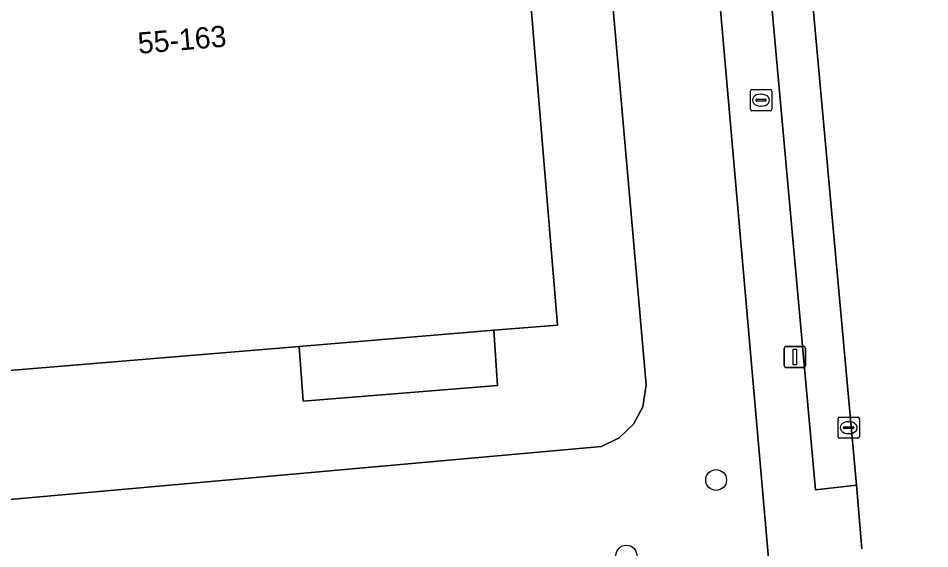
# Model space of a CAD drawing. Extents: x 162989 to 165008, y 383432 to 384338.
# Drawn here: x 164281.81 to 164324.59, y 383867.76 to 383892.69 of the extents above; entities that cross this region are included whole.
import ezdxf

# ---------------------------------------------------------------- set-up
doc = ezdxf.new("R2010")
doc.units = 0
for name, color, linetype in [('IMGEO_Boom', 7, 'Continuous'), ('IMGEO_Brandkraan', 7, 'Continuous'), ('IMGEO_Groenvoorziening', 7, 'Continuous'), ('IMGEO_Kolk', 7, 'Continuous'), ('IMGEO_Lichtmast', 7, 'Continuous'), ('IMGEO_Pand', 7, 'Continuous'), ('IMGEO_Pand_nummerreeks', 7, 'Continuous'), ('IMGEO_Parkeervlak_open', 7, 'Continuous'), ('IMGEO_Rijbaan_lokaal_open', 7, 'Continuous'), ('IMGEO_Voetpad_open', 7, 'Continuous')]:
    doc.layers.add(name, color=color, linetype=linetype)

msp = doc.modelspace()

# ---------------------------------------------------------------- linework, layer by layer
at = {"layer": 'IMGEO_Boom'}
for centre in [(164314.563, 383870.989), (164310.352, 383867.439)]:
    msp.add_circle(centre, 0.489, dxfattribs=at)
at = {"layer": 'IMGEO_Brandkraan'}
for p, q in [((164316.244, 383889.335), (164317.096, 383889.335)), ((164316.169, 383888.409), (164316.169, 383889.261)), ((164316.657, 383889.115), (164316.682, 383889.115)), ((164317.17, 383889.261), (164317.17, 383888.409)), ((164316.428, 383888.829), (164316.428, 383888.841)), ((164316.866, 383888.792), (164316.468, 383888.792)), ((164316.471, 383888.878), (164316.869, 383888.878)), ((164316.68, 383888.555), (164316.655, 383888.555)), ((164316.912, 383888.841), (164316.912, 383888.829)), ((164317.096, 383888.335), (164316.244, 383888.335))]:
    msp.add_line(p, q, dxfattribs=at)
for points in [[(164316.244, 383889.335), (164317.096, 383889.335)], [(164316.169, 383888.409), (164316.169, 383889.261)], [(164317.17, 383889.261), (164317.17, 383888.409)], [(164317.096, 383888.335), (164316.244, 383888.335)]]:
    msp.add_lwpolyline(points, dxfattribs=at)
for centre, radius, start, end in [((164316.246, 383889.259), 0.0765, 91.552, 178.448), ((164316.246, 383889.259), 0.0765, 91.552, 178.448), ((164317.094, 383889.259), 0.0765, 1.552, 88.448), ((164317.094, 383889.259), 0.0765, 1.552, 88.448), ((164316.468, 383888.838), 0.0403, 85.8775, 175.7526), ((164316.465, 383888.828), 0.0366, 178.938, 274.7102), ((164316.869, 383888.835), 0.043, 264.8664, 352.4533), ((164316.873, 383888.84), 0.0386, 1.7309, 96.639), ((164316.246, 383888.411), 0.0765, 181.552, 268.448), ((164316.246, 383888.411), 0.0765, 181.552, 268.448), ((164317.094, 383888.411), 0.0765, 271.552, 358.448), ((164317.094, 383888.411), 0.0765, 271.552, 358.448)]:
    msp.add_arc(centre, radius, start, end, dxfattribs=at)
for centre, major_axis, ratio, start_param, end_param in [((164316.656, 383888.835), (-0.387, 0.002), 0.722429, 4.712389, 7.853982), ((164316.681, 383888.835), (-0.39, 0.002), 0.717154, 1.570796, 4.712389)]:
    msp.add_ellipse(centre, major_axis=major_axis, ratio=ratio, start_param=start_param, end_param=end_param, dxfattribs=at)
at = {"layer": 'IMGEO_Groenvoorziening'}
for points in [[(164311.621, 383906.595), (164309.285, 383906.355), (164307.801, 383906.262), (164304.812, 383906.003), (164307.113, 383878.271), (164304.123, 383878.023), (164304.31, 383875.425), (164295.181, 383874.701), (164294.997, 383877.265), (164276.472, 383875.728), (164274.745, 383896.542)], [(164271.417, 383894.215), (164273.539, 383869.365), (164309.188, 383872.569), (164310.019, 383872.973), (164310.684, 383873.614), (164311.118, 383874.429), (164311.279, 383875.468), (164308.972, 383901.858), (164313.975, 383902.213), (164313.728, 383905.024)], [(164317.115, 383866.231), (164313.975, 383902.213), (164308.972, 383901.858), (164311.279, 383875.468), (164311.118, 383874.429), (164310.684, 383873.614), (164310.019, 383872.973), (164309.188, 383872.569), (164273.539, 383869.365), (164274.024, 383863.683)]]:
    msp.add_lwpolyline(points, dxfattribs=at)
at = {"layer": 'IMGEO_Kolk'}
for p, q in [((164320.361, 383873.948), (164321.213, 383873.948)), ((164320.286, 383873.022), (164320.286, 383873.874)), ((164320.588, 383873.491), (164320.986, 383873.491)), ((164320.774, 383873.728), (164320.799, 383873.728)), ((164321.287, 383873.874), (164321.287, 383873.022)), ((164320.545, 383873.442), (164320.545, 383873.454)), ((164320.983, 383873.405), (164320.585, 383873.405)), ((164320.797, 383873.168), (164320.772, 383873.168)), ((164321.029, 383873.454), (164321.029, 383873.442)), ((164321.213, 383872.948), (164320.361, 383872.948))]:
    msp.add_line(p, q, dxfattribs=at)
for points in [[(164320.361, 383873.948), (164321.213, 383873.948)], [(164320.286, 383873.022), (164320.286, 383873.874)], [(164321.287, 383873.874), (164321.287, 383873.022)], [(164321.213, 383872.948), (164320.361, 383872.948)]]:
    msp.add_lwpolyline(points, dxfattribs=at)
for centre, radius, start, end in [((164320.363, 383873.872), 0.0765, 91.552, 178.448), ((164320.363, 383873.872), 0.0765, 91.552, 178.448), ((164321.211, 383873.872), 0.0765, 1.552, 88.448), ((164321.211, 383873.872), 0.0765, 1.552, 88.448), ((164320.585, 383873.451), 0.0403, 85.8775, 175.7526), ((164320.99, 383873.453), 0.0386, 1.7309, 96.639), ((164320.582, 383873.441), 0.0366, 178.938, 274.7102), ((164320.986, 383873.448), 0.043, 264.8664, 352.4533), ((164320.363, 383873.024), 0.0765, 181.552, 268.448), ((164320.363, 383873.024), 0.0765, 181.552, 268.448), ((164321.211, 383873.024), 0.0765, 271.552, 358.448), ((164321.211, 383873.024), 0.0765, 271.552, 358.448)]:
    msp.add_arc(centre, radius, start, end, dxfattribs=at)
for centre, major_axis, ratio, start_param, end_param in [((164320.773, 383873.448), (-0.387, 0.002), 0.722429, 4.712389, 7.853982), ((164320.798, 383873.448), (-0.39, 0.002), 0.717154, 1.570796, 4.712389)]:
    msp.add_ellipse(centre, major_axis=major_axis, ratio=ratio, start_param=start_param, end_param=end_param, dxfattribs=at)
at = {"layer": 'IMGEO_Lichtmast'}
for p, q in [((164317.76, 383876.368), (164317.76, 383877.168)), ((164317.76, 383877.168), (164317.76, 383876.368)), ((164317.86, 383877.268), (164318.65, 383877.268)), ((164318.65, 383877.268), (164317.86, 383877.268)), ((164318.75, 383877.168), (164318.75, 383876.368)), ((164318.75, 383876.368), (164318.75, 383877.168)), ((164318.65, 383876.268), (164317.86, 383876.268)), ((164317.86, 383876.268), (164318.65, 383876.268))]:
    msp.add_line(p, q, dxfattribs=at)
msp.add_lwpolyline([(164318.18, 383877.143), (164318.33, 383877.143), (164318.33, 383876.393), (164318.18, 383876.393), (164318.18, 383877.143)], dxfattribs=at)
for centre, start, end in [((164317.86, 383877.168), 90, 180), ((164317.86, 383877.168), 90, 180), ((164318.65, 383877.168), 0, 90), ((164318.65, 383877.168), 360, 90), ((164317.86, 383876.368), 180, 270), ((164317.86, 383876.368), 180, 270), ((164318.65, 383876.368), 270, 0), ((164318.65, 383876.368), 270, 0)]:
    msp.add_arc(centre, 0.1, start, end, dxfattribs=at)
at = {"layer": 'IMGEO_Pand'}
msp.add_lwpolyline([(164284.046, 383897.183), (164284.035, 383897.313), (164274.745, 383896.542), (164276.472, 383875.728), (164294.997, 383877.265), (164304.123, 383878.023), (164307.113, 383878.271), (164304.812, 383906.003), (164295.481, 383905.229), (164295.924, 383899.945), (164296.082, 383898.042), (164296.192, 383896.714), (164288.624, 383896.086), (164288.762, 383894.411), (164286.958, 383894.261), (164286.708, 383897.264), (164286.696, 383897.412)], close=True, dxfattribs=at)
at = {"layer": 'IMGEO_Parkeervlak_open'}
msp.add_lwpolyline([(164318.468, 383900.415), (164316.602, 383900.342), (164316.711, 383898.434), (164319.225, 383870.529), (164321.144, 383870.751)], close=True, dxfattribs=at)
at = {"layer": 'IMGEO_Rijbaan_lokaal_open'}
msp.add_lwpolyline([(164324.59, 383906.693), (164324.126, 383910.174), (164323.866, 383913.03), (164317.362, 383912.233), (164317.916, 383906.542), (164318.328, 383901.972), (164318.468, 383900.415), (164321.144, 383870.751), (164321.401, 383867.758)], dxfattribs=at)
at = {"layer": 'IMGEO_Voetpad_open'}
for points in [[(164314.65, 383940.623), (164312.756, 383962.237), (164312.458, 383965.638), (164308.636, 384009.259), (164304.479, 384010.176), (164305.459, 384000.449), (164306.559, 383987.731), (164307.7, 383976.698), (164308.433, 383968.687), (164308.664, 383965.869), (164308.709, 383965.318), (164308.987, 383961.924), (164309.037, 383961.321), (164309.165, 383959.76), (164309.846, 383951.777), (164310.616, 383942.636), (164310.744, 383939.756), (164312.069, 383924.637), (164312.836, 383915.887), (164313.429, 383909.127), (164313.728, 383905.024), (164313.975, 383902.213), (164317.115, 383866.231), (164319.438, 383861.849)], [(164321.401, 383867.758), (164321.144, 383870.751), (164319.225, 383870.529), (164316.711, 383898.434), (164316.602, 383900.342), (164318.468, 383900.415), (164318.328, 383901.972), (164317.916, 383906.542), (164317.362, 383912.233), (164316.375, 383920.84), (164315.487, 383930.342), (164314.65, 383940.623)]]:
    msp.add_lwpolyline(points, dxfattribs=at)
msp.add_lwpolyline([(164294.997, 383877.265), (164295.181, 383874.701), (164304.31, 383875.425), (164304.123, 383878.023)], close=True, dxfattribs=at)

# ---------------------------------------------------------------- texts
at = {"layer": 'IMGEO_Pand_nummerreeks'}
msp.add_text('55-163', height=1, rotation=4.7447, dxfattribs=at).set_placement((164287.464, 383891.012))

doc.saveas('drawing.dxf')
